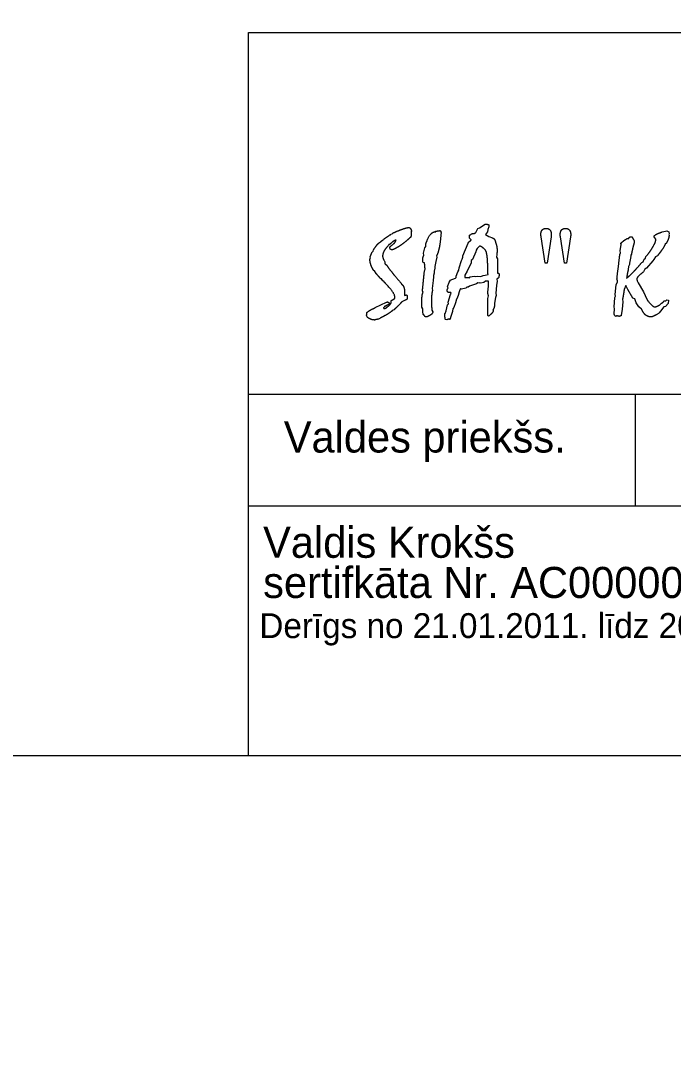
# Model space of a CAD drawing. Extents: x 728710 to 728960, y 272811 to 273475.
# Drawn here: x 728840.52 to 728861.5, y 273192.03 to 273225.7 of the extents above; entities that cross this region are included whole.
import ezdxf

# ---------------------------------------------------------------- set-up
doc = ezdxf.new("R2010")
doc.units = 0
doc.layers.add('RAMI_PLAN_####_TKST_#', color=7, linetype='Continuous')

msp = doc.modelspace()

# ---------------------------------------------------------------- linework, layer by layer
at = {"layer": 'RAMI_PLAN_####_TKST_#'}
for p, q in [((728847.845, 273225.332), (728912.915, 273225.332)), ((728847.845, 273202.048), (728847.845, 273225.332)), ((728847.845, 273213.69), (728885.901, 273213.69)), ((728860.289, 273210.09), (728860.289, 273213.69)), ((728847.845, 273210.09), (728885.901, 273210.09))]:
    msp.add_line(p, q, dxfattribs=at)
for points in [[(728728.89, 273202.048), (728728.89, 273475.126), (728912.915, 273475.126), (728912.915, 273202.048)], [(728709.938, 272811.037), (728959.516, 272811.036), (728959.516, 273202.048), (728709.939, 273202.048)]]:
    msp.add_lwpolyline(points, close=True, dxfattribs=at)
for points in [[(728855.155, 273218.894), (728855.221, 273219.023), (728855.275, 273219.047), (728855.454, 273219.161)], [(728855.576, 273219.077), (728855.538, 273218.985), (728855.527, 273218.916), (728855.473, 273218.825), (728855.579, 273218.763), (728855.69, 273218.718)], [(728852.425, 273218.835), (728852.465, 273218.846), (728852.483, 273218.872)], [(728853.083, 273218.938), (728853.083, 273218.93), (728853.08, 273218.934), (728853.08, 273218.876), (728853.076, 273218.854), (728853.074, 273218.848)], [(728853.814, 273218.912), (728853.844, 273218.904), (728853.874, 273218.931)], [(728855.01, 273218.655), (728854.948, 273218.713), (728854.954, 273218.806)], [(728855.023, 273218.853), (728855.026, 273218.855)], [(728857.452, 273217.902), (728857.387, 273217.902), (728857.256, 273218.759)], [(728857.581, 273218.757), (728857.452, 273217.902)], [(728858.073, 273217.902), (728858.009, 273217.902), (728857.877, 273218.759)], [(728858.205, 273218.759), (728858.073, 273217.902)], [(728860.152, 273218.756), (728860.178, 273218.756)], [(728860.944, 273218.683), (728860.884, 273218.76)], [(728861.151, 273218.913), (728861.261, 273218.932), (728861.301, 273218.951), (728861.37, 273218.917), (728861.377, 273218.855), (728861.362, 273218.833), (728861.373, 273218.794)], [(728852.18, 273218.656), (728852.188, 273218.674)], [(728852.388, 273218.51), (728852.36, 273218.503), (728852.345, 273218.475)], [(728853.054, 273218.732), (728853.02, 273218.712), (728853.003, 273218.693)], [(728853.462, 273218.114), (728853.48, 273218.165), (728853.473, 273218.223), (728853.516, 273218.402), (728853.546, 273218.445), (728853.551, 273218.531)], [(728854.268, 273217.105), (728854.242, 273217.148), (728854.298, 273217.298), (728854.333, 273217.335), (728854.333, 273217.361), (728854.501, 273217.42), (728854.52, 273217.442), (728854.52, 273217.485), (728854.582, 273217.631), (728854.615, 273217.683), (728854.619, 273217.76), (728854.696, 273217.997), (728854.716, 273218.032), (728854.742, 273218.098), (728854.739, 273218.139), (728854.907, 273218.552)], [(728855.275, 273218.457), (728855.198, 273218.38), (728855.163, 273218.322), (728855.159, 273218.266), (728855.053, 273218.029), (728855.006, 273217.997), (728855.006, 273217.92), (728854.881, 273217.646), (728854.808, 273217.519), (728854.804, 273217.442)], [(728859.789, 273218.182), (728859.816, 273218.242), (728859.801, 273218.308), (728859.831, 273218.508), (728859.819, 273218.541)], [(728860.015, 273218.695), (728860.075, 273218.702)], [(728861.286, 273218.553), (728861.243, 273218.515), (728861.209, 273218.424)], [(728851.764, 273218.067), (728851.76, 273218.112)], [(728851.814, 273218.25), (728851.855, 273218.295), (728851.867, 273218.338)], [(728852.396, 273218.368), (728852.388, 273218.39)], [(728853.891, 273218.138), (728853.902, 273218.097), (728853.87, 273217.955), (728853.836, 273217.795), (728853.84, 273217.741), (728853.818, 273217.653), (728853.821, 273217.587), (728853.797, 273217.514), (728853.797, 273217.462), (728853.779, 273217.35), (728853.756, 273217.094), (728853.76, 273217.029)], [(728855.495, 273218.255), (728855.462, 273218.331)], [(728855.834, 273218.182), (728855.824, 273218.102), (728855.849, 273218.051)], [(728860.163, 273218.199), (728860.137, 273218.147), (728860.144, 273218.121), (728860.096, 273217.906), (728860.1, 273217.861), (728860.064, 273217.803), (728860.06, 273217.698)], [(728860.494, 273217.925), (728860.542, 273217.953), (728860.574, 273218.033), (728860.619, 273218.067), (728860.63, 273218.117)], [(728860.998, 273218.143), (728860.94, 273218.11), (728860.888, 273218.022), (728860.849, 273217.979), (728860.643, 273217.749), (728860.593, 273217.711), (728860.55, 273217.624)], [(728852.207, 273217.989), (728852.224, 273217.948), (728852.224, 273217.937), (728852.224, 273217.92)], [(728853.508, 273217.92), (728853.458, 273217.929)], [(728855.546, 273217.642), (728855.538, 273217.696), (728855.546, 273217.756), (728855.546, 273217.887), (728855.527, 273217.913)], [(728851.947, 273217.569), (728851.902, 273217.656), (728851.874, 273217.668), (728851.84, 273217.71), (728851.84, 273217.725)], [(728852.212, 273217.298), (728852.199, 273217.324), (728852.169, 273217.339), (728852.119, 273217.397), (728852.096, 273217.404)], [(728853.497, 273217.582), (728853.512, 273217.692), (728853.527, 273217.711)], [(728854.804, 273217.442), (728854.918, 273217.45), (728854.948, 273217.438), (728854.976, 273217.463), (728855.101, 273217.485), (728855.148, 273217.474), (728855.198, 273217.492), (728855.316, 273217.481), (728855.396, 273217.511), (728855.462, 273217.519), (728855.557, 273217.543)], [(728855.828, 273217.393), (728855.841, 273217.332), (728855.824, 273217.19), (728855.802, 273216.941), (728855.806, 273216.864), (728855.787, 273216.803), (728855.761, 273216.616), (728855.761, 273216.578)], [(728855.849, 273217.634), (728855.849, 273217.584), (728855.893, 273217.584)], [(728859.698, 273216.21), (728859.666, 273216.187), (728859.629, 273216.206), (728859.61, 273216.26), (728859.621, 273216.451), (728859.61, 273216.488), (728859.633, 273216.802), (728859.651, 273216.845), (728859.64, 273216.9), (728859.67, 273217.214), (728859.717, 273217.309), (728859.713, 273217.339), (728859.698, 273217.397)], [(728855.561, 273216.2), (728855.546, 273216.222), (728855.546, 273216.412), (728855.542, 273216.642), (728855.546, 273216.765), (728855.561, 273216.853), (728855.538, 273216.93), (728855.553, 273217.109), (728855.565, 273217.133), (728855.561, 273217.328), (728855.473, 273217.324), (728855.415, 273217.288), (728855.316, 273217.262), (728855.275, 273217.277), (728855.258, 273217.262), (728855.224, 273217.273), (728855.174, 273217.243), (728854.954, 273217.167), (728854.907, 273217.133), (728854.868, 273217.133), (728854.83, 273217.105), (728854.692, 273217.071), (728854.662, 273217.079)], [(728860.486, 273216.424), (728860.398, 273216.497), (728860.318, 273216.634), (728860.268, 273216.758), (728860.213, 273216.784), (728860.049, 273217.061), (728859.984, 273217.19), (728859.928, 273217.061)], [(728860.348, 273217.339), (728860.374, 273217.274), (728860.546, 273216.984), (728860.658, 273216.743)], [(728852.863, 273216.87), (728852.9, 273216.879)], [(728852.943, 273216.861), (728852.943, 273216.831)], [(728853.467, 273216.259), (728853.447, 273216.348), (728853.451, 273216.433), (728853.424, 273216.492), (728853.424, 273216.601), (728853.424, 273216.743), (728853.424, 273216.777)], [(728853.458, 273216.967), (728853.439, 273217.021)], [(728854.165, 273216.283), (728854.202, 273216.367), (728854.249, 273216.565), (728854.275, 273216.593), (728854.271, 273216.649), (728854.341, 273216.903), (728854.359, 273216.933), (728854.355, 273216.963), (728854.279, 273216.959)], [(728854.535, 273216.743), (728854.505, 273216.627), (728854.451, 273216.474), (728854.417, 273216.437), (728854.406, 273216.356)], [(728859.877, 273216.743), (728859.881, 273216.659), (728859.862, 273216.421), (728859.834, 273216.217)], [(728861.089, 273216.575), (728861.132, 273216.62), (728861.185, 273216.65), (728861.205, 273216.689), (728861.265, 273216.696), (728861.304, 273216.73), (728861.355, 273216.715), (728861.342, 273216.605), (728861.261, 273216.516), (728861.202, 273216.501), (728861.093, 273216.359), (728861.06, 273216.305), (728861.048, 273216.297)], [(728851.891, 273216.459), (728851.913, 273216.478), (728852.281, 273216.648)], [(728852.203, 273216.485), (728852.19, 273216.464)], [(728852.323, 273216.558), (728852.3, 273216.55), (728852.272, 273216.528)], [(728852.433, 273216.649), (728852.433, 273216.663), (728852.433, 273216.677)], [(728852.525, 273216.408), (728852.495, 273216.397), (728852.465, 273216.367)], [(728852.885, 273216.711), (728852.779, 273216.659), (728852.762, 273216.642)], [(728853.745, 273216.427), (728853.745, 273216.389), (728853.775, 273216.344)], [(728851.668, 273216.159), (728851.648, 273216.199)], [(728851.655, 273216.289), (728851.653, 273216.306)], [(728851.898, 273216.075), (728851.882, 273216.079), (728851.87, 273216.079)], [(728852.089, 273216.144), (728852.07, 273216.126), (728852.046, 273216.118), (728852.029, 273216.103)], [(728852.246, 273216.221), (728852.238, 273216.225)], [(728854.219, 273216.082), (728854.176, 273216.097)]]:
    msp.add_lwpolyline(points, dxfattribs=at)
for points in [[(728855.454, 273219.161), (728855.54, 273219.161), (728855.56, 273219.148)], [(728855.56, 273219.148), (728855.579, 273219.135), (728855.579, 273219.092)], [(728855.579, 273219.083), (728855.578, 273219.079), (728855.576, 273219.077)], [(728855.579, 273219.092), (728855.579, 273219.086), (728855.579, 273219.083)], [(728852.188, 273218.674), (728852.267, 273218.732), (728852.394, 273218.815)], [(728852.394, 273218.815), (728852.416, 273218.828), (728852.425, 273218.835)], [(728852.483, 273218.872), (728852.659, 273218.953), (728852.777, 273218.996)], [(728852.777, 273218.996), (728852.895, 273219.039), (728852.969, 273219.05)], [(728852.969, 273219.05), (728852.977, 273219.052), (728852.983, 273219.053)], [(728852.983, 273219.053), (728852.99, 273219.054), (728852.996, 273219.054)], [(728852.996, 273219.054), (728853.033, 273219.054), (728853.058, 273219.013)], [(728853.07, 273218.772), (728853.065, 273218.755), (728853.054, 273218.732)], [(728853.058, 273219.013), (728853.083, 273218.971), (728853.083, 273218.938)], [(728853.076, 273218.8), (728853.076, 273218.788), (728853.07, 273218.772)], [(728853.074, 273218.848), (728853.074, 273218.835), (728853.075, 273218.824)], [(728853.075, 273218.824), (728853.076, 273218.813), (728853.076, 273218.8)], [(728853.579, 273218.609), (728853.674, 273218.878), (728853.814, 273218.912)], [(728853.874, 273218.931), (728853.915, 273218.942), (728853.947, 273218.947)], [(728853.947, 273218.947), (728853.978, 273218.953), (728854.001, 273218.953)], [(728854.038, 273218.861), (728854.008, 273218.54), (728853.976, 273218.387)], [(728854.001, 273218.953), (728854.02, 273218.953), (728854.029, 273218.931)], [(728854.029, 273218.931), (728854.038, 273218.908), (728854.038, 273218.861)], [(728854.954, 273218.806), (728854.982, 273218.819), (728855.023, 273218.853)], [(728855.026, 273218.855), (728855.041, 273218.856), (728855.069, 273218.858)], [(728855.069, 273218.858), (728855.135, 273218.862), (728855.155, 273218.894)], [(728857.249, 273218.836), (728857.249, 273218.925), (728857.294, 273218.976)], [(728857.251, 273218.808), (728857.249, 273218.824), (728857.249, 273218.836)], [(728857.256, 273218.759), (728857.253, 273218.791), (728857.251, 273218.808)], [(728857.294, 273218.976), (728857.338, 273219.026), (728857.417, 273219.026)], [(728857.417, 273219.026), (728857.499, 273219.026), (728857.542, 273218.975)], [(728857.542, 273218.975), (728857.585, 273218.923), (728857.585, 273218.828)], [(728857.584, 273218.784), (728857.583, 273218.77), (728857.581, 273218.757)], [(728857.585, 273218.828), (728857.585, 273218.798), (728857.584, 273218.784)], [(728857.873, 273218.828), (728857.873, 273218.923), (728857.915, 273218.975)], [(728857.874, 273218.786), (728857.873, 273218.8), (728857.873, 273218.828)], [(728857.877, 273218.759), (728857.875, 273218.772), (728857.874, 273218.786)], [(728857.915, 273218.975), (728857.958, 273219.026), (728858.039, 273219.026)], [(728858.039, 273219.026), (728858.118, 273219.026), (728858.164, 273218.976)], [(728858.164, 273218.976), (728858.209, 273218.925), (728858.209, 273218.836)], [(728858.208, 273218.79), (728858.207, 273218.774), (728858.205, 273218.759)], [(728858.209, 273218.836), (728858.209, 273218.806), (728858.208, 273218.79)], [(728860.075, 273218.702), (728860.09, 273218.734), (728860.105, 273218.745)], [(728860.105, 273218.745), (728860.12, 273218.756), (728860.152, 273218.756)], [(728860.178, 273218.756), (728860.189, 273218.73), (728860.221, 273218.681)], [(728860.884, 273218.76), (728860.906, 273218.82), (728861.05, 273218.874)], [(728861.05, 273218.874), (728861.114, 273218.897), (728861.151, 273218.913)], [(728861.373, 273218.794), (728861.368, 273218.736), (728861.346, 273218.677)], [(728851.867, 273218.338), (728851.93, 273218.441), (728851.984, 273218.502)], [(728851.984, 273218.502), (728852.038, 273218.562), (728852.096, 273218.594)], [(728852.096, 273218.594), (728852.109, 273218.613), (728852.128, 273218.627)], [(728852.128, 273218.627), (728852.147, 273218.641), (728852.18, 273218.656)], [(728852.345, 273218.475), (728852.252, 273218.383), (728852.205, 273218.299)], [(728852.501, 273218.609), (728852.454, 273218.575), (728852.388, 273218.51)], [(728852.388, 273218.39), (728852.388, 273218.405), (728852.394, 273218.419)], [(728852.394, 273218.419), (728852.399, 273218.433), (728852.411, 273218.448)], [(728852.411, 273218.448), (728852.425, 273218.46), (728852.448, 273218.476)], [(728852.448, 273218.476), (728852.586, 273218.577), (728852.586, 273218.652)], [(728852.74, 273218.484), (728852.603, 273218.39), (728852.48, 273218.338)], [(728852.586, 273218.652), (728852.549, 273218.643), (728852.501, 273218.609)], [(728853.003, 273218.693), (728852.878, 273218.577), (728852.74, 273218.484)], [(728853.551, 273218.531), (728853.56, 273218.557), (728853.579, 273218.609)], [(728854.907, 273218.552), (728854.924, 273218.587), (728854.964, 273218.614)], [(728854.964, 273218.614), (728855.004, 273218.64), (728855.01, 273218.655)], [(728855.353, 273218.425), (728855.316, 273218.449), (728855.275, 273218.457)], [(728855.462, 273218.331), (728855.391, 273218.401), (728855.353, 273218.425)], [(728855.69, 273218.718), (728855.733, 273218.709), (728855.756, 273218.674)], [(728855.756, 273218.674), (728855.779, 273218.64), (728855.791, 273218.569)], [(728855.791, 273218.569), (728855.817, 273218.505), (728855.829, 273218.441)], [(728855.829, 273218.441), (728855.841, 273218.376), (728855.841, 273218.296)], [(728859.819, 273218.541), (728859.857, 273218.582), (728859.906, 273218.622)], [(728859.906, 273218.622), (728859.956, 273218.661), (728860.015, 273218.695)], [(728860.238, 273218.519), (728860.217, 273218.448), (728860.199, 273218.37)], [(728860.221, 273218.681), (728860.253, 273218.631), (728860.253, 273218.596)], [(728860.241, 273218.538), (728860.238, 273218.525), (728860.238, 273218.519)], [(728860.253, 273218.596), (728860.253, 273218.579), (728860.241, 273218.538)], [(728860.63, 273218.117), (728860.77, 273218.283), (728860.859, 273218.441)], [(728860.859, 273218.441), (728860.948, 273218.599), (728860.948, 273218.668)], [(728860.948, 273218.679), (728860.948, 273218.682), (728860.944, 273218.683)], [(728860.948, 273218.668), (728860.948, 273218.676), (728860.948, 273218.679)], [(728861.209, 273218.424), (728861.138, 273218.325), (728861.091, 273218.262)], [(728861.346, 273218.677), (728861.325, 273218.618), (728861.286, 273218.553)], [(728851.753, 273218.041), (728851.756, 273218.054), (728851.764, 273218.067)], [(728851.76, 273218.112), (728851.766, 273218.127), (728851.785, 273218.175)], [(728851.785, 273218.175), (728851.805, 273218.222), (728851.814, 273218.25)], [(728852.205, 273218.299), (728852.158, 273218.215), (728852.158, 273218.135)], [(728852.158, 273218.135), (728852.158, 273218.103), (728852.17, 273218.067)], [(728852.17, 273218.067), (728852.182, 273218.032), (728852.207, 273217.989)], [(728852.427, 273218.343), (728852.411, 273218.351), (728852.396, 273218.368)], [(728852.457, 273218.334), (728852.444, 273218.334), (728852.427, 273218.343)], [(728852.469, 273218.335), (728852.465, 273218.334), (728852.457, 273218.334)], [(728852.48, 273218.338), (728852.474, 273218.336), (728852.469, 273218.335)], [(728853.447, 273218.024), (728853.447, 273218.036), (728853.456, 273218.082)], [(728853.456, 273218.082), (728853.46, 273218.103), (728853.462, 273218.114)], [(728853.976, 273218.387), (728853.943, 273218.234), (728853.891, 273218.138)], [(728855.522, 273218.12), (728855.512, 273218.193), (728855.495, 273218.255)], [(728855.531, 273217.993), (728855.531, 273218.047), (728855.522, 273218.12)], [(728855.836, 273218.227), (728855.834, 273218.197), (728855.834, 273218.182)], [(728855.841, 273218.296), (728855.841, 273218.281), (728855.836, 273218.227)], [(728859.744, 273217.803), (728859.778, 273218.065), (728859.789, 273218.182)], [(728860.199, 273218.37), (728860.182, 273218.293), (728860.163, 273218.199)], [(728861.091, 273218.262), (728861.045, 273218.199), (728860.998, 273218.143)], [(728851.749, 273218.017), (728851.749, 273218.028), (728851.753, 273218.041)], [(728851.768, 273217.896), (728851.749, 273217.965), (728851.749, 273218.017)], [(728851.822, 273217.748), (728851.786, 273217.828), (728851.768, 273217.896)], [(728851.836, 273217.74), (728851.831, 273217.746), (728851.822, 273217.748)], [(728851.84, 273217.725), (728851.84, 273217.735), (728851.836, 273217.74)], [(728852.224, 273217.92), (728852.224, 273217.901), (728852.239, 273217.882)], [(728852.239, 273217.882), (728852.255, 273217.864), (728852.28, 273217.856)], [(728852.28, 273217.856), (728852.33, 273217.772), (728852.45, 273217.622)], [(728853.45, 273217.984), (728853.447, 273218.008), (728853.447, 273218.024)], [(728853.458, 273217.929), (728853.452, 273217.961), (728853.45, 273217.984)], [(728853.515, 273217.823), (728853.51, 273217.873), (728853.508, 273217.92)], [(728853.527, 273217.711), (728853.519, 273217.772), (728853.515, 273217.823)], [(728855.527, 273217.913), (728855.529, 273217.935), (728855.53, 273217.953)], [(728855.53, 273217.953), (728855.531, 273217.971), (728855.531, 273217.993)], [(728855.849, 273218.051), (728855.849, 273218.034), (728855.85, 273218.004)], [(728855.852, 273217.762), (728855.849, 273217.683), (728855.849, 273217.634)], [(728855.85, 273218.004), (728855.856, 273217.904), (728855.856, 273217.872)], [(728855.856, 273217.872), (728855.856, 273217.842), (728855.852, 273217.762)], [(728859.698, 273217.397), (728859.709, 273217.541), (728859.744, 273217.803)], [(728860.241, 273217.641), (728860.361, 273217.767), (728860.494, 273217.925)], [(728852.024, 273217.488), (728851.986, 273217.529), (728851.947, 273217.569)], [(728852.096, 273217.404), (728852.061, 273217.447), (728852.024, 273217.488)], [(728852.45, 273217.622), (728852.569, 273217.471), (728852.751, 273217.266)], [(728853.475, 273217.368), (728853.486, 273217.483), (728853.497, 273217.582)], [(728855.538, 273217.595), (728855.538, 273217.606), (728855.544, 273217.631)], [(728855.542, 273217.579), (728855.538, 273217.592), (728855.538, 273217.595)], [(728855.557, 273217.543), (728855.546, 273217.567), (728855.542, 273217.579)], [(728855.544, 273217.631), (728855.544, 273217.636), (728855.546, 273217.642)], [(728855.865, 273217.415), (728855.852, 273217.405), (728855.828, 273217.393)], [(728855.89, 273217.438), (728855.878, 273217.425), (728855.865, 273217.415)], [(728855.895, 273217.463), (728855.892, 273217.448), (728855.89, 273217.438)], [(728855.893, 273217.584), (728855.901, 273217.558), (728855.903, 273217.544)], [(728855.905, 273217.519), (728855.905, 273217.504), (728855.895, 273217.463)], [(728855.903, 273217.544), (728855.905, 273217.53), (728855.905, 273217.519)], [(728860.008, 273217.42), (728860.12, 273217.515), (728860.241, 273217.641)], [(728860.035, 273217.591), (728860.023, 273217.528), (728860.008, 273217.42)], [(728860.06, 273217.698), (728860.047, 273217.653), (728860.035, 273217.591)], [(728860.383, 273217.481), (728860.333, 273217.427), (728860.333, 273217.394)], [(728860.333, 273217.394), (728860.333, 273217.381), (728860.342, 273217.356)], [(728860.55, 273217.624), (728860.434, 273217.534), (728860.383, 273217.481)], [(728852.287, 273217.215), (728852.238, 273217.268), (728852.212, 273217.298)], [(728852.549, 273216.827), (728852.549, 273216.939), (728852.287, 273217.215)], [(728852.751, 273217.266), (728852.758, 273217.245), (728852.771, 273217.229)], [(728852.771, 273217.229), (728852.784, 273217.214), (728852.809, 273217.197)], [(728852.809, 273217.197), (728852.839, 273217.143), (728852.853, 273217.089)], [(728852.853, 273217.089), (728852.867, 273217.036), (728852.867, 273216.971)], [(728853.439, 273217.021), (728853.464, 273217.253), (728853.475, 273217.368)], [(728854.232, 273217.032), (728854.234, 273217.051), (728854.241, 273217.066)], [(728854.241, 273217.066), (728854.247, 273217.081), (728854.268, 273217.105)], [(728854.662, 273217.079), (728854.641, 273217.067), (728854.612, 273216.952)], [(728859.928, 273217.061), (728859.913, 273216.949), (728859.901, 273216.874)], [(728860.342, 273217.356), (728860.346, 273217.345), (728860.348, 273217.339)], [(728852.444, 273216.711), (728852.472, 273216.724), (728852.498, 273216.739)], [(728852.498, 273216.739), (728852.525, 273216.754), (728852.545, 273216.769)], [(728852.545, 273216.769), (728852.547, 273216.782), (728852.548, 273216.794)], [(728852.548, 273216.794), (728852.549, 273216.806), (728852.549, 273216.827)], [(728852.866, 273216.916), (728852.865, 273216.892), (728852.863, 273216.87)], [(728852.867, 273216.971), (728852.867, 273216.939), (728852.866, 273216.916)], [(728852.933, 273216.74), (728852.919, 273216.724), (728852.885, 273216.711)], [(728852.9, 273216.879), (728852.904, 273216.881), (728852.909, 273216.884)], [(728852.909, 273216.884), (728852.913, 273216.887), (728852.915, 273216.887)], [(728852.915, 273216.887), (728852.925, 273216.887), (728852.932, 273216.879)], [(728852.932, 273216.879), (728852.94, 273216.872), (728852.943, 273216.861)], [(728852.951, 273216.784), (728852.947, 273216.756), (728852.933, 273216.74)], [(728852.943, 273216.831), (728852.943, 273216.827), (728852.946, 273216.812)], [(728852.946, 273216.812), (728852.949, 273216.797), (728852.951, 273216.784)], [(728853.424, 273216.777), (728853.424, 273216.84), (728853.433, 273216.885)], [(728853.433, 273216.885), (728853.441, 273216.93), (728853.458, 273216.967)], [(728853.734, 273216.846), (728853.726, 273216.745), (728853.726, 273216.59)], [(728853.76, 273217.029), (728853.741, 273216.947), (728853.734, 273216.846)], [(728854.243, 273216.996), (728854.232, 273217.013), (728854.232, 273217.032)], [(728854.279, 273216.959), (728854.255, 273216.978), (728854.243, 273216.996)], [(728854.612, 273216.952), (728854.583, 273216.836), (728854.535, 273216.743)], [(728859.901, 273216.874), (728859.888, 273216.799), (728859.877, 273216.743)], [(728860.658, 273216.743), (728860.669, 273216.726), (728860.692, 273216.696)], [(728851.723, 273216.373), (728851.792, 273216.418), (728851.891, 273216.459)], [(728852.19, 273216.464), (728852.192, 273216.461), (728852.197, 273216.455)], [(728852.197, 273216.455), (728852.209, 273216.448), (728852.216, 273216.448)], [(728852.227, 273216.515), (728852.212, 273216.506), (728852.203, 273216.485)], [(728852.216, 273216.448), (728852.255, 273216.448), (728852.344, 273216.524)], [(728852.272, 273216.528), (728852.242, 273216.524), (728852.227, 273216.515)], [(728852.281, 273216.648), (728852.291, 273216.653), (728852.299, 273216.656)], [(728852.299, 273216.656), (728852.308, 273216.659), (728852.315, 273216.659)], [(728852.315, 273216.659), (728852.332, 273216.659), (728852.351, 273216.641)], [(728852.357, 273216.583), (728852.345, 273216.569), (728852.323, 273216.558)], [(728852.344, 273216.524), (728852.433, 273216.601), (728852.433, 273216.649)], [(728852.351, 273216.641), (728852.369, 273216.623), (728852.369, 273216.612)], [(728852.369, 273216.612), (728852.369, 273216.597), (728852.357, 273216.583)], [(728852.433, 273216.677), (728852.433, 273216.685), (728852.436, 273216.693)], [(728852.436, 273216.693), (728852.439, 273216.702), (728852.444, 273216.711)], [(728852.66, 273216.535), (728852.603, 273216.479), (728852.525, 273216.408)], [(728852.762, 273216.642), (728852.717, 273216.592), (728852.66, 273216.535)], [(728853.726, 273216.59), (728853.726, 273216.562), (728853.73, 273216.524)], [(728853.73, 273216.524), (728853.734, 273216.487), (728853.745, 273216.427)], [(728855.748, 273216.493), (728855.735, 273216.45), (728855.707, 273216.401)], [(728855.707, 273216.401), (728855.71, 273216.392), (728855.712, 273216.382)], [(728855.712, 273216.382), (728855.714, 273216.371), (728855.714, 273216.367)], [(728855.761, 273216.578), (728855.761, 273216.537), (728855.748, 273216.493)], [(728860.608, 273216.247), (728860.557, 273216.293), (728860.486, 273216.424)], [(728860.692, 273216.696), (728860.841, 273216.498), (728860.91, 273216.498)], [(728860.91, 273216.498), (728860.938, 273216.498), (728860.983, 273216.517)], [(728860.983, 273216.517), (728861.028, 273216.536), (728861.089, 273216.575)], [(728851.644, 273216.233), (728851.644, 273216.25), (728851.647, 273216.264)], [(728851.646, 273216.217), (728851.644, 273216.229), (728851.644, 273216.233)], [(728851.648, 273216.199), (728851.648, 273216.205), (728851.646, 273216.217)], [(728851.647, 273216.264), (728851.649, 273216.278), (728851.655, 273216.289)], [(728851.653, 273216.306), (728851.655, 273216.328), (728851.723, 273216.373)], [(728851.78, 273216.099), (728851.73, 273216.118), (728851.668, 273216.159)], [(728851.87, 273216.079), (728851.829, 273216.079), (728851.78, 273216.099)], [(728851.959, 273216.093), (728851.926, 273216.086), (728851.898, 273216.075)], [(728852.029, 273216.103), (728851.992, 273216.099), (728851.959, 273216.093)], [(728852.172, 273216.182), (728852.138, 273216.163), (728852.089, 273216.144)], [(728852.238, 273216.225), (728852.207, 273216.201), (728852.172, 273216.182)], [(728852.35, 273216.286), (728852.296, 273216.251), (728852.246, 273216.221)], [(728852.465, 273216.367), (728852.403, 273216.322), (728852.35, 273216.286)], [(728853.507, 273216.209), (728853.486, 273216.242), (728853.467, 273216.259)], [(728853.549, 273216.176), (728853.529, 273216.176), (728853.507, 273216.209)], [(728853.604, 273216.186), (728853.575, 273216.176), (728853.549, 273216.176)], [(728853.672, 273216.221), (728853.633, 273216.196), (728853.604, 273216.186)], [(728853.745, 273216.278), (728853.723, 273216.25), (728853.672, 273216.221)], [(728853.775, 273216.344), (728853.767, 273216.306), (728853.745, 273216.278)], [(728854.161, 273216.233), (728854.161, 273216.254), (728854.162, 273216.265)], [(728854.164, 273216.18), (728854.161, 273216.209), (728854.161, 273216.233)], [(728854.162, 273216.265), (728854.163, 273216.276), (728854.165, 273216.283)], [(728854.176, 273216.097), (728854.167, 273216.151), (728854.164, 273216.18)], [(728854.253, 273216.094), (728854.236, 273216.089), (728854.219, 273216.082)], [(728854.286, 273216.101), (728854.27, 273216.099), (728854.253, 273216.094)], [(728854.309, 273216.099), (728854.301, 273216.101), (728854.286, 273216.101)], [(728854.322, 273216.097), (728854.316, 273216.097), (728854.309, 273216.099)], [(728854.358, 273216.208), (728854.339, 273216.147), (728854.322, 273216.097)], [(728854.406, 273216.356), (728854.378, 273216.269), (728854.358, 273216.208)], [(728855.583, 273216.216), (728855.568, 273216.205), (728855.561, 273216.2)], [(728855.714, 273216.367), (728855.714, 273216.315), (728855.583, 273216.216)], [(728859.72, 273216.204), (728859.705, 273216.208), (728859.698, 273216.21)], [(728859.767, 273216.194), (728859.754, 273216.194), (728859.72, 273216.204)], [(728859.795, 273216.2), (728859.778, 273216.194), (728859.767, 273216.194)], [(728859.834, 273216.217), (728859.812, 273216.206), (728859.795, 273216.2)], [(728860.729, 273216.183), (728860.658, 273216.2), (728860.608, 273216.247)], [(728860.758, 273216.178), (728860.746, 273216.179), (728860.729, 273216.183)], [(728860.779, 273216.176), (728860.77, 273216.176), (728860.758, 273216.178)], [(728861.048, 273216.297), (728860.858, 273216.176), (728860.779, 273216.176)]]:
    msp.add_open_spline(points, degree=2, dxfattribs=at)

# ---------------------------------------------------------------- texts
for s, height, rotation, p in [('Valdes priekšs.', 1, 359.9999, (728848.979, 273211.811)), ('Valdis Krokšs', 1, 359.9999, (728848.314, 273208.423)), ('sertifkāta Nr. AC000000071', 1, 359.9999, (728848.314, 273207.129)), ('Derīgs no 21.01.2011. līdz 20.01.2016.', 0.8, 0.0269, (728848.193, 273205.837))]:
    msp.add_text(s, height=height, rotation=rotation, dxfattribs=at).set_placement(p)

doc.saveas('drawing.dxf')
